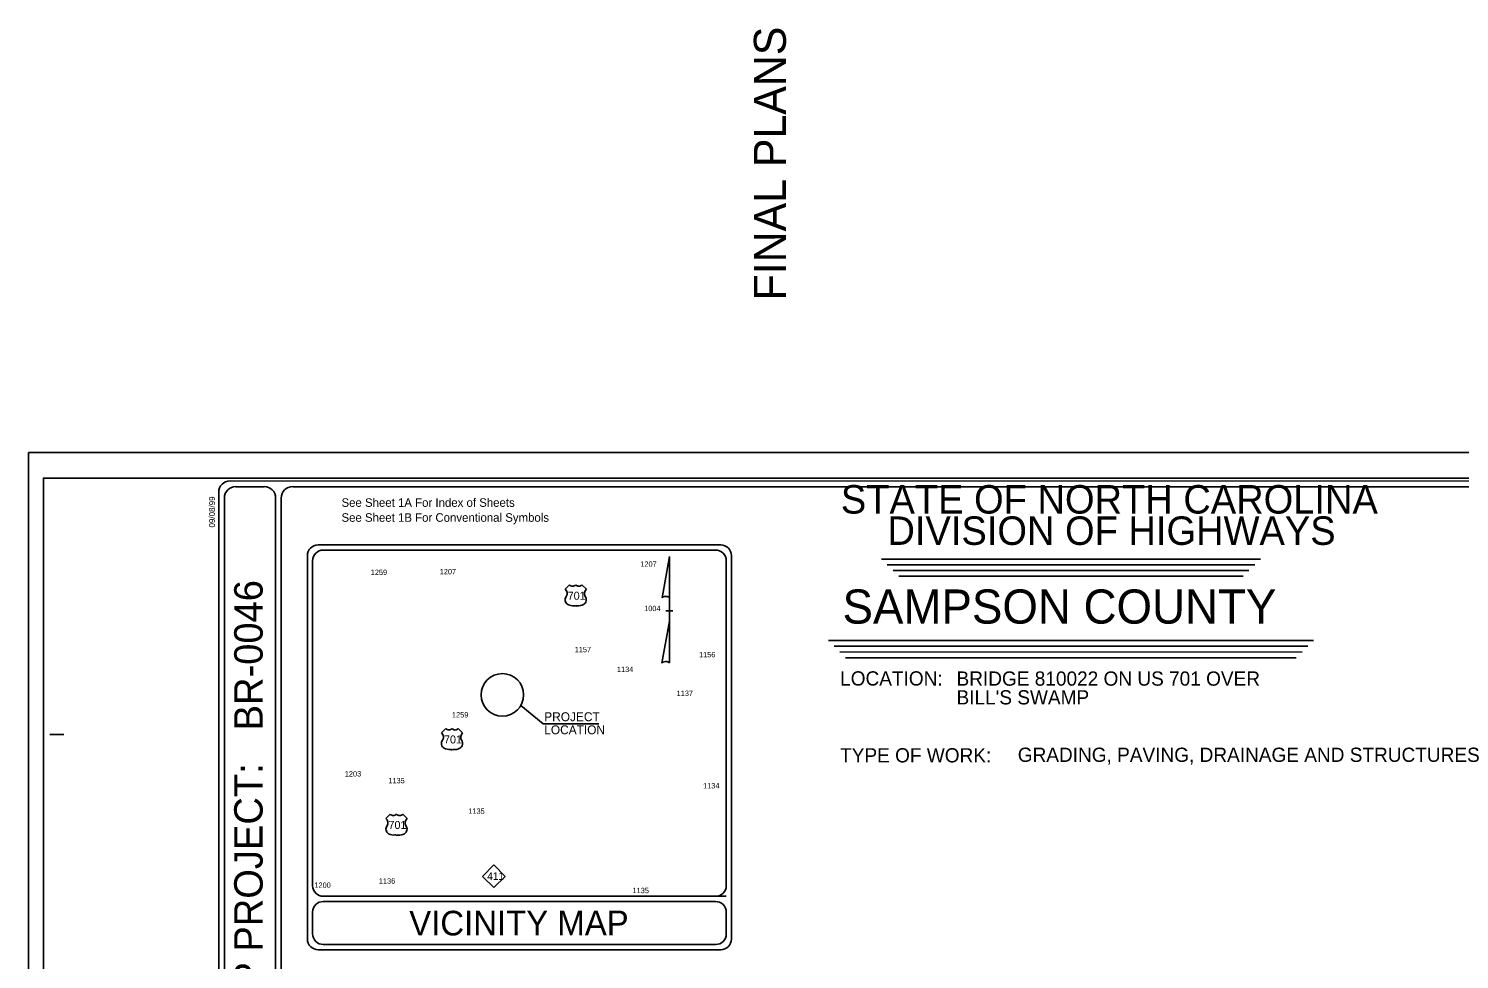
# Model space of a CAD drawing. Extents: x 2163579 to 2286010, y 210234 to 425257.
# Drawn here: x 2163579 to 2244027, y 372954 to 425257 of the extents above; entities that cross this region are included whole.
import ezdxf

# ---------------------------------------------------------------- set-up
doc = ezdxf.new("R2010")
doc.units = 0
for name, color, linetype in [('Default', 7, 'Continuous'), ('Prop North Arrow for Plan Sheets CELL', 7, 'Continuous'), ('Prop PHM Highway Shield CELL', 7, 'Continuous'), ('Sheet Cutting Line CELL', 7, 'Continuous'), ('Sheet Data Field CELL', 7, 'Continuous'), ('Sheet Plot Border Inside CELL', 7, 'Continuous'), ('Sheet Plot Border Outside CELL', 7, 'Continuous'), ('Sheet Title CELL', 7, 'Continuous'), ('Sheet Title Data Points CELL', 7, 'Continuous'), ('Typical Text Label CELL', 7, 'Continuous')]:
    doc.layers.add(name, color=color, linetype=linetype)

msp = doc.modelspace()

# ---------------------------------------------------------------- linework, layer by layer
at = {"layer": 'Prop North Arrow for Plan Sheets CELL'}
for p, q in [((2199195, 393276), (2199605, 395594)), ((2199607, 395594), (2199605, 395594)), ((2199607, 395594), (2199605, 395594)), ((2199607, 395594), (2199607, 393204)), ((2199607, 391964), (2199607, 393274)), ((2199607, 393204), (2199607, 393271)), ((2199607, 391964), (2199190, 389601)), ((2199407, 392544), (2199405, 392544)), ((2199585, 392544), (2199407, 392544)), ((2199410, 392544), (2199810, 392544)), ((2199610, 389611), (2199607, 391964))]:
    msp.add_line(p, q, dxfattribs=at)
for centre, start_param, end_param in [((2199401, 393251), 0.216388, 2.908219), ((2199401, 389593), 0.201328, 3.141593)]:
    msp.add_ellipse(centre, major_axis=(212, -2), ratio=0.461098, start_param=start_param, end_param=end_param, dxfattribs=at)
at = {"layer": 'Prop PHM Highway Shield CELL'}
for p, q in [((2193991, 394001), (2193745, 393755)), ((2194939, 393755), (2194693, 393998)), ((2187036, 385925), (2186790, 385679)), ((2187984, 385679), (2187738, 385922)), ((2183914, 381119), (2183668, 380873)), ((2184862, 380873), (2184616, 381116)), ((2189737, 378258), (2189092, 377613)), ((2190367, 377613), (2189737, 378258)), ((2189092, 377613), (2189737, 376983)), ((2189737, 376983), (2190367, 377613))]:
    msp.add_line(p, q, dxfattribs=at)
for centre, radius, start, end in [((2193542, 393512), 317, 328.14003, 50.03889), ((2194164, 394152), 230, 221.07884, 319.54959), ((2194519, 394149), 230, 220.45041, 318.98937), ((2195141, 393509), 317, 129.52467, 211.85997), ((2194047, 393157), 301, 141.54338, 240.59781), ((2194188, 393444), 621, 242.31376, 275.88587), ((2194272, 392741), 87.9, 36.50071, 103.56218), ((2194411, 392738), 87.9, 76.43376, 141.13275), ((2194495, 393441), 621, 264.12561, 297.68624), ((2194636, 393154), 301, 299.40219, 38.46205), ((2186587, 385436), 317, 328.14003, 50.03889), ((2187209, 386076), 230, 221.07884, 319.54959), ((2187564, 386073), 230, 220.45041, 318.98937), ((2188186, 385433), 317, 129.52467, 211.85997), ((2187092, 385081), 301, 141.54338, 240.59781), ((2187233, 385368), 621, 242.31376, 275.88587), ((2187317, 384665), 87.9, 36.50071, 103.56218), ((2187456, 384663), 87.9, 76.43376, 141.13275), ((2187540, 385365), 621, 264.12561, 297.68624), ((2187681, 385078), 301, 299.40219, 38.46205), ((2183465, 380631), 317, 328.14003, 50.03889), ((2184087, 381270), 230, 221.07884, 319.54959), ((2184442, 381267), 230, 220.45041, 318.98937), ((2185064, 380628), 317, 129.52467, 211.85997), ((2183970, 380276), 301, 141.54338, 240.59781), ((2184111, 380562), 621, 242.31376, 275.88587), ((2184195, 379860), 87.9, 36.50071, 103.56218), ((2184334, 379857), 87.9, 76.43376, 141.13275), ((2184418, 380560), 621, 264.12561, 297.68624), ((2184559, 380273), 301, 299.40219, 38.46205)]:
    msp.add_arc(centre, radius, start, end, dxfattribs=at)
at = {"layer": 'Sheet Cutting Line CELL'}
for q in [(2271355, 401435), (2163579, 331036)]:
    msp.add_line((2163579, 401435), q, dxfattribs=at)
at = {"layer": 'Sheet Plot Border Inside CELL'}
msp.add_lwpolyline([(2164411, 332472), (2271067, 332472), (2271067, 399999), (2164411, 399999)], close=True, dxfattribs=at)
at = {"layer": 'Sheet Plot Border Outside CELL'}
msp.add_lwpolyline([(2271355, 401435), (2163579, 401435), (2163579, 331036), (2271355, 331036)], close=True, dxfattribs=at)
at = {"layer": 'Sheet Title CELL'}
for p, q in [((2177467, 333596), (2177467, 398876)), ((2177787, 345436), (2177787, 398876)), ((2179858, 396242), (2202496, 396242)), ((2202204, 395953), (2180150, 395953)), ((2179254, 374093), (2179254, 395645)), ((2179546, 395356), (2179546, 377093)), ((2202808, 377093), (2202808, 395356)), ((2203100, 395645), (2203100, 374091)), ((2211541, 395448), (2232837, 395449)), ((2211861, 395129), (2232517, 395128)), ((2212181, 394808), (2232197, 394809)), ((2212501, 394488), (2231877, 394489)), ((2208555, 390867), (2235819, 390866)), ((2208875, 390547), (2235499, 390546)), ((2209195, 390226), (2235179, 390227)), ((2209515, 389907), (2234859, 389906)), ((2191252, 387214), (2192517, 386191)), ((2192517, 386191), (2195633, 386191)), ((2164763, 385595), (2165563, 385595)), ((2164763, 385595), (2165563, 385595)), ((2180150, 376496), (2202204, 376496)), ((2180150, 376207), (2202204, 376207)), ((2202204, 376496), (2202808, 376496)), ((2179546, 374384), (2179546, 375609)), ((2202808, 375609), (2202808, 374384)), ((2202496, 373494), (2179858, 373494)), ((2202204, 373787), (2180150, 373787))]:
    msp.add_line(p, q, dxfattribs=at)
for points in [[(2269628, 399835), (2174906, 399836)], [(2174267, 399196), (2174267, 333276)], [(2174267, 399196), (2174267, 333276)], [(2176827, 399515), (2175227, 399516)], [(2269307, 399515), (2178428, 399515)], [(2174588, 398876), (2174587, 333596)]]:
    msp.add_lwpolyline(points, dxfattribs=at)
msp.add_circle((2190216, 387815), 1198, dxfattribs=at)
for centre, start, end in [((2174907, 399199), 90, 180), ((2175227, 398879), 90, 180), ((2176827, 398879), 0, 90), ((2178427, 398879), 90, 180)]:
    msp.add_arc(centre, 640, start, end, dxfattribs=at)
for centre, major_axis, start_param, end_param in [((2179858, 395645), (-603, 0), 4.712388, 6.283184), ((2180150, 395356), (-603, 0), 4.712388, 6.283184), ((2202204, 395356), (-603, 0), 3.141592, 4.712389), ((2202496, 395645), (-603, 0), 3.141592, 4.712388), ((2180150, 377093), (-603, 0), 6.283184, 7.853982), ((2202204, 377093), (603, 0), 4.712389, 6.283184), ((2180150, 375609), (-603, 0), 4.712389, 6.283184), ((2202204, 375609), (-603, 0), 3.141592, 4.712389), ((2179858, 374091), (-603, 0), 6.280053, 7.853982), ((2180150, 374384), (-603, 0), 6.283184, 7.853982), ((2202204, 374384), (603, 0), 4.712389, 6.283184), ((2202496, 374091), (603, 0), 4.712389, 6.283184)]:
    msp.add_ellipse(centre, major_axis=major_axis, ratio=0.989741, start_param=start_param, end_param=end_param, dxfattribs=at)
at = {"layer": 'Sheet Title Data Points CELL'}
msp.add_line((2229969, 388341), (2229969, 388341), dxfattribs=at)

# ---------------------------------------------------------------- texts
at = {"layer": 'Default'}
msp.add_text('FINAL PLANS', height=1800, rotation=90, dxfattribs=at).set_placement((2206158, 409984))
at = {"layer": 'Prop PHM Highway Shield CELL'}
for s, height, p in [('701', 450, (2193893, 393164)), ('701', 450, (2186938, 385088)), ('701', 450, (2183816, 380282)), ('411', 420, (2189366, 377421))]:
    msp.add_text(s, height=height, dxfattribs=at).set_placement(p)
at = {"layer": 'Sheet Data Field CELL'}
msp.add_text('SAMPSON COUNTY', height=1920, rotation=360, dxfattribs=at).set_placement((2209342, 391820))
for s, p in [('BRIDGE 810022 ON US 701 OVER', (2215753, 388334)), ("BILL'S SWAMP", (2215753, 387279)), ('GRADING, PAVING, DRAINAGE AND STRUCTURES', (2219196, 384051))]:
    msp.add_text(s, height=800.01, dxfattribs=at).set_placement(p)
at = {"layer": 'Sheet Title CELL'}
for s, height, rotation, p in [('STATE OF NORTH CAROLINA', 1599.99, 360, (2209249, 398005)), ('09/08/99', 336, 90, (2174059, 397220)), ('See Sheet 1A For Index of Sheets', 480, 360, (2181172, 398384)), ('See Sheet 1B For Conventional Symbols', 480, 360, (2181172, 397544)), ('DIVISION OF HIGHWAYS', 1599.99, 360, (2211867, 396246)), ('BR-0046', 1600, 90, (2176738, 385823)), ('LOCATION: ', 800, 360, (2209208, 388342)), ('TYPE OF WORK:', 800.01, 360, (2209208, 384021)), ('TIP PROJECT:', 1600, 90, (2176738, 369467))]:
    msp.add_text(s, height=height, rotation=rotation, dxfattribs=at).set_placement(p)
for s, height, p in [('1207', 300, (2197973, 395016)), ('1259', 300, (2182815, 394553)), ('1207', 300, (2186694, 394592)), ('1004', 300, (2198189, 392523)), ('1157', 300, (2194285, 390213)), ('1156', 300, (2201274, 389926)), ('1134', 300, (2196659, 389102)), ('1137', 300, (2200015, 387756)), ('1259', 300, (2187383, 386548)), ('PROJECT', 500, (2192572, 386339)), ('LOCATION', 500, (2192572, 385604)), ('1203', 300, (2181356, 383230)), ('1135', 300, (2183806, 382847)), ('1134', 300, (2201501, 382559)), ('1135', 300, (2188301, 381135)), ('1136', 300, (2183272, 377210)), ('1200', 300, (2179648, 376975)), ('1135', 300, (2197536, 376674))]:
    msp.add_text(s, height=height, dxfattribs=at).set_placement(p)
at = {"layer": 'Typical Text Label CELL'}
msp.add_text('VICINITY MAP', height=1383.94, rotation=0.08951, dxfattribs=at).set_placement((2184981, 374295))

doc.saveas('drawing.dxf')
